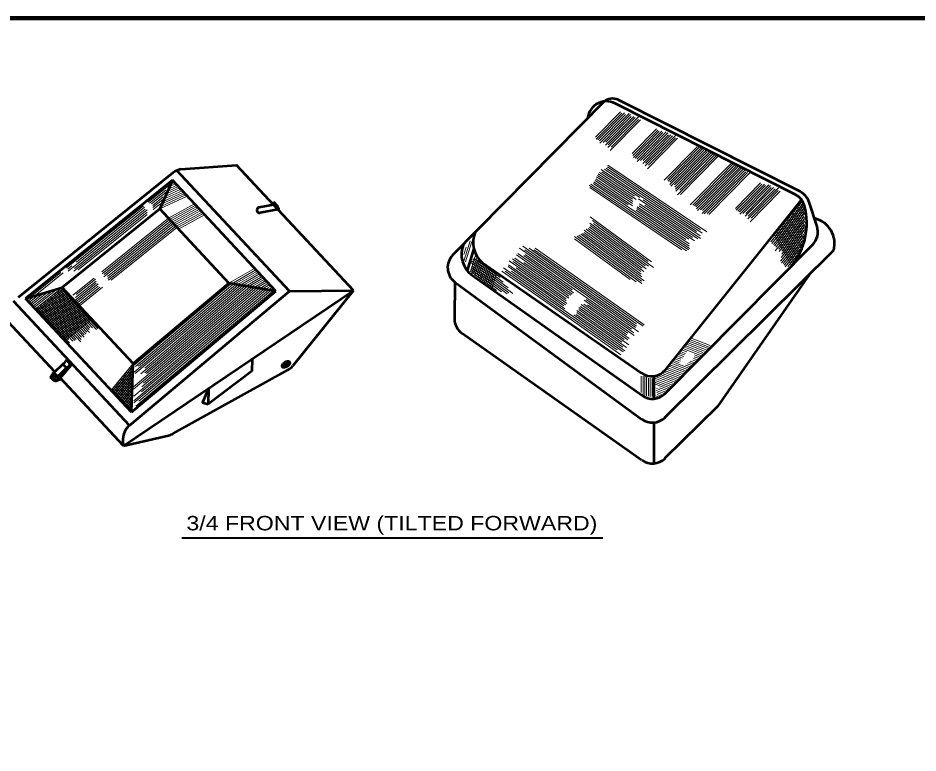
# Model space of a CAD drawing. Extents: x -94 to 619, y -64 to 390.
# Drawn here: x 121.7 to 371.6, y 180.4 to 384.5 of the extents above; entities that cross this region are included whole.
import ezdxf

# ---------------------------------------------------------------- set-up
doc = ezdxf.new("R2010")
doc.units = 0
doc.layers.add('1', color=7, linetype='Continuous', lineweight=13)

msp = doc.modelspace()

# ---------------------------------------------------------------- linework, layer by layer
at = {"layer": '1', "lineweight": 53}
for p, q in [((242.429, 318.693), (284.722, 361.553)), ((337.504, 335.457), (288.089, 360.43)), ((338.855, 336.269), (288.755, 361.588)), ((166.939, 342.485), (182.369, 343.629)), ((214.86, 308.786), (182.369, 343.629)), ((164.707, 341.463), (121.696, 306.859)), ((197.065, 308.614), (165.693, 342.257)), ((164.571, 339.428), (123.814, 306.638)), ((164.571, 339.428), (161.056, 331.467)), ((193.249, 308.675), (164.571, 339.428)), ((192.643, 332.611), (188.705, 331.907)), ((192.643, 332.611), (192.643, 333.478)), ((192.643, 333.478), (193.861, 332.172)), ((192.643, 333.111), (193.861, 331.805)), ((301.482, 286.796), (339.241, 334.004)), ((343.558, 326.638), (341.351, 333.365)), ((161.056, 331.467), (133.971, 309.675)), ((180.282, 310.849), (161.056, 331.467)), ((193.861, 331.305), (188.969, 330.43)), ((193.861, 331.305), (193.861, 332.172)), ((248.263, 320.485), (246.399, 314.394)), ((301.284, 273.599), (348.185, 319.998)), ((301.399, 280.208), (342.324, 321.525)), ((250.594, 316.631), (294.693, 285.981)), ((247.916, 312.964), (294.923, 279.733)), ((153.687, 288.533), (180.282, 310.849)), ((193.249, 308.675), (180.282, 310.849)), ((243.028, 311.151), (242.889, 301.051)), ((243.028, 311.151), (294.808, 273.124)), ((123.814, 306.638), (133.971, 309.675)), ((153.687, 288.533), (133.971, 309.675)), ((151.024, 265.729), (214.86, 308.786)), ((153.229, 275.094), (193.249, 308.675)), ((214.86, 308.786), (198.026, 287.947)), ((152.635, 271.333), (120.47, 305.825)), ((153.229, 275.094), (123.814, 306.638)), ((131.907, 286.229), (117.606, 301.565)), ((294.834, 261.694), (245.003, 296.898)), ((134.136, 288.39), (131.684, 286.012)), ((136.466, 288.11), (133.181, 284.291)), ((134.136, 288.39), (135.18, 287.313)), ((135.139, 289.525), (136.183, 288.448)), ((153.229, 275.094), (153.687, 288.533)), ((186.673, 289.774), (186.625, 286.395)), ((195.047, 287.697), (197.024, 289.115)), ((195.193, 287.494), (197.17, 288.912)), ((132.315, 283.962), (130.976, 285.188)), ((132.433, 284.609), (131.332, 285.71)), ((132.745, 284.951), (131.684, 286.012)), ((135.18, 287.313), (132.745, 284.951)), ((164.792, 269.106), (196.561, 286.715)), ((186.625, 286.395), (174.495, 277.305)), ((298.249, 285.047), (298.249, 278.776)), ((131.996, 283.561), (130.731, 284.719)), ((133.767, 284.235), (131.996, 283.561)), ((133.181, 284.291), (132.085, 283.874)), ((151.024, 265.729), (133.437, 284.588)), ((174.556, 281.601), (174.495, 277.305)), ((298.249, 272.177), (298.249, 260.805)), ((151.024, 265.729), (163.493, 268.607))]:
    msp.add_line(p, q, dxfattribs=at)
at = {"layer": '1'}
for p, q in [((282.068, 351.398), (289.033, 358.456)), ((282.248, 350.868), (289.389, 358.105)), ((282.724, 350.639), (290.118, 358.132)), ((283.175, 350.384), (290.426, 357.732)), ((283.255, 349.753), (291.355, 357.962)), ((284.158, 349.957), (291.801, 357.702)), ((284.815, 349.198), (292.654, 357.142)), ((284.908, 350.005), (291.964, 357.155)), ((285.522, 348.492), (293.987, 357.069)), ((285.565, 349.247), (293.058, 356.84)), ((286.127, 347.681), (294.502, 356.168)), ((286.394, 348.663), (293.954, 356.324)), ((292.218, 346.825), (299.033, 353.731)), ((292.423, 346.321), (299.388, 353.38)), ((292.603, 345.792), (299.744, 353.029)), ((293.079, 345.562), (300.474, 353.056)), ((293.531, 345.308), (300.782, 352.656)), ((293.611, 344.677), (301.711, 352.886)), ((294.514, 344.88), (302.157, 352.626)), ((295.17, 344.122), (303.009, 352.066)), ((295.264, 344.928), (302.32, 352.079)), ((295.878, 343.416), (304.342, 351.993)), ((295.92, 344.17), (303.413, 351.764)), ((296.483, 342.605), (304.858, 351.092)), ((296.75, 343.587), (304.309, 351.248)), ((301.143, 339.497), (310.259, 348.735)), ((302.018, 339.672), (310.86, 348.632)), ((302.248, 339.193), (311.41, 348.478)), ((302.677, 338.916), (311.887, 348.25)), ((302.706, 338.233), (312.142, 347.796)), ((302.99, 337.809), (312.645, 347.594)), ((304.007, 338.128), (313.074, 347.316)), ((304.115, 337.525), (313.674, 347.212)), ((304.244, 336.944), (314.103, 346.935)), ((304.375, 336.366), (314.533, 346.66)), ((304.834, 335.407), (315.636, 346.353)), ((305.423, 336.715), (315.158, 346.581)), ((305.608, 335.479), (315.987, 345.998)), ((283.667, 342.454), (311.085, 323.959)), ((284.512, 342.487), (310.081, 325.239)), ((285.014, 342.751), (311.648, 324.785)), ((285.347, 343.13), (311.215, 325.68)), ((285.519, 343.617), (312.943, 325.118)), ((308.36, 332.574), (319.733, 344.099)), ((309.038, 332.548), (320.384, 344.047)), ((309.565, 332.37), (320.764, 343.72)), ((309.921, 332.019), (321.267, 343.517)), ((310.073, 331.462), (321.496, 343.038)), ((310.401, 331.083), (322.125, 342.963)), ((311.205, 331.185), (322.627, 342.76)), ((311.73, 331.006), (322.981, 342.407)), ((282.315, 340.35), (292.398, 333.548)), ((282.581, 340.774), (292.299, 334.219)), ((282.798, 341.231), (293.313, 334.137)), ((283.121, 341.616), (292.848, 335.054)), ((283.766, 341.784), (294.327, 334.66)), ((311.659, 330.222), (323.485, 342.206)), ((312.239, 330.097), (323.765, 341.778)), ((313.013, 330.171), (324.268, 341.576)), ((313.517, 329.969), (324.869, 341.473)), ((163.547, 337.963), (157.813, 333.35)), ((166.187, 337.695), (163.195, 336.312)), ((165.828, 338.08), (163.501, 337.004)), ((165.469, 338.465), (163.806, 337.696)), ((165.11, 338.85), (164.112, 338.388)), ((164.751, 339.235), (164.417, 339.081)), ((280.292, 338.096), (307.327, 319.859)), ((280.463, 337.378), (305.996, 320.154)), ((280.794, 338.361), (307.896, 320.078)), ((281.492, 338.493), (308.131, 320.523)), ((281.625, 339.007), (291.164, 332.572)), ((281.958, 339.385), (292.343, 332.379)), ((282.147, 339.86), (292.364, 332.968)), ((320.909, 331.638), (327.874, 338.696)), ((321.089, 331.108), (328.23, 338.345)), ((321.565, 330.879), (328.959, 338.372)), ((322.016, 330.624), (329.267, 337.972)), ((322.096, 329.993), (330.196, 338.202)), ((322.999, 330.197), (330.642, 337.942)), ((323.656, 329.438), (331.495, 337.382)), ((323.749, 330.245), (330.805, 337.396)), ((162.718, 336.654), (158.228, 333.042)), ((162.863, 336.129), (158.793, 332.854)), ((168.699, 335.001), (161.056, 331.467)), ((168.34, 335.386), (161.362, 332.159)), ((167.981, 335.771), (161.667, 332.851)), ((167.622, 336.156), (161.973, 333.543)), ((167.263, 336.541), (162.278, 334.236)), ((166.904, 336.926), (162.584, 334.928)), ((166.546, 337.31), (162.889, 335.62)), ((324.364, 328.732), (332.828, 337.31)), ((324.406, 329.487), (331.899, 337.08)), ((324.969, 327.921), (333.344, 336.409)), ((325.235, 328.903), (332.795, 336.564)), ((162.034, 334.82), (159.101, 332.46)), ((161.984, 334.139), (159.116, 331.831)), ((161.35, 332.987), (159.236, 331.286)), ((171.031, 332.5), (163.801, 328.523)), ((294.012, 334.269), (310.456, 323.176)), ((294.305, 332.865), (309.549, 322.582)), ((295.285, 334.013), (311.176, 323.294)), ((295.738, 332.502), (309.017, 323.544)), ((330.777, 322.382), (339.77, 333.09)), ((330.831, 323.223), (339.388, 333.412)), ((338.074, 332.625), (340.712, 327.829)), ((338.419, 333.036), (340.654, 328.971)), ((338.763, 333.446), (340.499, 330.29)), ((339.108, 333.857), (340.173, 331.921)), ((156.537, 332.323), (135.164, 315.128)), ((157.037, 331.442), (135.633, 314.222)), ((157.55, 330.571), (137.242, 314.232)), ((157.523, 331.191), (137.365, 314.973)), ((156.836, 331.922), (137.935, 316.715)), ((157.546, 329.926), (138.415, 314.534)), ((171.383, 332.123), (164.153, 328.146)), ((171.734, 331.746), (164.505, 327.769)), ((172.086, 331.369), (164.856, 327.392)), ((172.438, 330.992), (165.208, 327.014)), ((172.79, 330.615), (165.56, 326.637)), ((173.141, 330.238), (165.912, 326.26)), ((293.335, 331.107), (308.098, 321.149)), ((293.552, 331.564), (308.101, 321.75)), ((293.657, 332.096), (307.115, 323.018)), ((294.186, 332.342), (307.951, 323.057)), ((331.025, 321.899), (339.753, 332.292)), ((331.448, 321.625), (339.86, 331.642)), ((331.749, 321.206), (339.921, 330.937)), ((332.08, 320.823), (340.09, 330.361)), ((336.005, 330.161), (340.098, 322.72)), ((336.35, 330.572), (340.273, 323.439)), ((336.695, 330.983), (340.426, 324.2)), ((337.039, 331.393), (340.552, 325.008)), ((337.477, 331.634), (340.647, 325.873)), ((337.729, 332.214), (340.703, 326.807)), ((163.791, 328.534), (145.056, 313.46)), ((164.475, 327.8), (145.555, 312.578)), ((164.133, 328.167), (145.612, 313.265)), ((164.817, 327.434), (146.529, 312.72)), ((173.493, 329.86), (166.263, 325.883)), ((280.504, 327.53), (296.724, 315.618)), ((280.607, 329.315), (297.631, 316.813)), ((281.254, 328.219), (296.657, 316.908)), ((281.453, 327.453), (298.117, 315.215)), ((331.901, 319.832), (339.89, 329.345)), ((332.968, 320.325), (339.971, 328.664)), ((333.074, 319.674), (339.94, 327.85)), ((333.936, 327.698), (338.696, 319.045)), ((334.281, 328.109), (338.964, 319.595)), ((334.626, 328.519), (339.22, 320.167)), ((334.971, 328.93), (339.463, 320.763)), ((335.315, 329.34), (339.691, 321.385)), ((335.66, 329.751), (339.904, 322.036)), ((165.159, 327.067), (146.657, 312.181)), ((165.501, 326.7), (146.861, 311.704)), ((165.843, 326.334), (147.593, 311.651)), ((278.938, 325.578), (294.6, 314.075)), ((278.948, 324.95), (294.744, 313.349)), ((279.452, 325.821), (295.445, 314.075)), ((280.027, 326.019), (295.015, 315.011)), ((280.347, 326.404), (296.098, 314.836)), ((280.543, 326.88), (295.842, 315.645)), ((331.867, 325.234), (336.866, 316.147)), ((332.212, 325.645), (337.195, 316.587)), ((332.557, 326.056), (337.514, 317.044)), ((332.902, 326.466), (337.825, 317.517)), ((333.246, 326.877), (338.125, 318.007)), ((333.591, 327.287), (338.416, 318.516)), ((333.611, 317.981), (339.99, 325.577)), ((333.756, 318.931), (340.087, 326.47)), ((333.775, 319.731), (340.069, 327.226)), ((247.204, 322.618), (245.475, 316.969)), ((247.682, 322.472), (245.953, 316.823)), ((276.217, 323.854), (293.383, 311.247)), ((276.265, 323.199), (291.681, 311.877)), ((276.994, 323.904), (294.924, 310.736)), ((277.432, 324.202), (294.855, 311.407)), ((277.933, 324.455), (295.544, 311.521)), ((278.447, 324.698), (294.948, 312.579)), ((331.523, 324.824), (336.504, 315.767)), ((333.4, 316.952), (339.533, 324.256)), ((333.687, 316.517), (339.925, 323.944)), ((334.175, 316.32), (339.406, 322.549)), ((246.136, 320.837), (245.513, 318.8)), ((278.244, 308.42), (260.967, 320.552)), ((293.479, 298.943), (261.884, 321.13)), ((293.164, 298.554), (262.441, 320.128)), ((292.627, 300.153), (263.601, 320.535)), ((295.3, 298.887), (265.022, 320.148)), ((295.601, 299.286), (265.309, 320.557)), ((334.415, 315.828), (339.494, 321.877)), ((334.713, 315.405), (338.808, 320.281)), ((248.831, 318.876), (247.376, 314.12)), ((249.061, 317.917), (247.703, 313.482)), ((247.997, 317.389), (256.441, 311.187)), ((249.442, 317.453), (248.207, 313.42)), ((248.293, 317.792), (255.595, 312.429)), ((271.994, 308.532), (259.016, 317.645)), ((268.896, 311.318), (259.665, 317.8)), ((275.576, 307.85), (260.137, 318.691)), ((275.969, 308.184), (260.445, 319.085)), ((275.598, 309.056), (262.138, 318.507)), ((293.449, 299.575), (264.735, 319.739)), ((335.475, 315.536), (337.874, 318.392)), ((136.627, 315.663), (135.541, 314.789)), ((180.282, 310.849), (187.393, 314.954)), ((247.405, 316.583), (259.09, 308.001)), ((247.576, 315.217), (257.539, 307.9)), ((247.701, 316.986), (257.82, 309.554)), ((247.745, 315.712), (258.007, 308.176)), ((249.756, 316.77), (248.592, 312.967)), ((250.15, 316.351), (249.025, 312.676)), ((250.531, 315.887), (249.423, 312.267)), ((250.949, 315.543), (249.799, 311.785)), ((251.392, 315.284), (250.25, 311.553)), ((251.852, 315.077), (250.721, 311.382)), ((252.33, 314.931), (251.132, 311.017)), ((275.91, 301.505), (256.494, 315.139)), ((268.997, 307.582), (257.756, 315.475)), ((269.479, 307.854), (257.92, 315.971)), ((268.298, 309.905), (258.044, 317.106)), ((269.087, 309.962), (259.172, 316.924)), ((274.096, 305.223), (259.998, 315.123)), ((268.494, 312.211), (262.178, 316.646)), ((133.587, 313.859), (125.534, 307.38)), ((134.198, 313.709), (126.893, 307.832)), ((181.057, 310.719), (187.743, 314.579)), ((181.832, 310.589), (188.093, 314.204)), ((182.607, 310.459), (188.443, 313.828)), ((183.382, 310.329), (188.793, 313.453)), ((184.157, 310.2), (189.143, 313.078)), ((184.932, 310.07), (189.493, 312.703)), ((247.299, 314.179), (254.529, 308.87)), ((247.42, 314.71), (255.959, 308.44)), ((252.808, 314.785), (251.538, 310.635)), ((253.286, 314.638), (251.974, 310.35)), ((253.764, 314.492), (252.438, 310.158)), ((253.951, 313.392), (252.834, 309.743)), ((254.425, 313.234), (253.247, 309.383)), ((275.672, 301.061), (256.959, 314.202)), ((268.345, 307.428), (258.72, 314.187)), ((143.385, 310.832), (136.878, 305.597)), ((142.801, 312.287), (136.915, 307.552)), ((143.949, 310.645), (137.191, 305.207)), ((143.968, 310.018), (137.505, 304.818)), ((143.358, 311.452), (137.673, 306.878)), ((143.197, 311.964), (137.884, 307.69)), ((153.986, 286.173), (182.78, 310.334)), ((154.008, 288.15), (180.835, 310.66)), ((154.265, 285.755), (183.428, 310.225)), ((154.329, 287.767), (181.387, 310.471)), ((155.137, 287.791), (182.131, 310.443)), ((155.8, 285.737), (184.725, 310.008)), ((156.878, 287.294), (184.076, 310.116)), ((156.878, 285.989), (185.373, 309.899)), ((185.707, 309.94), (189.843, 312.327)), ((186.482, 309.81), (190.192, 311.952)), ((187.257, 309.68), (190.542, 311.577)), ((188.032, 309.55), (190.892, 311.202)), ((188.807, 309.42), (191.243, 310.826)), ((189.582, 309.29), (191.593, 310.451)), ((190.356, 309.16), (191.942, 310.076)), ((273.932, 305.949), (268.298, 309.905)), ((273.56, 308.654), (268.494, 312.211)), ((273.952, 306.546), (269.087, 309.962)), ((126.353, 307.397), (124.498, 305.904)), ((127.623, 307.777), (124.84, 305.538)), ((128.893, 308.157), (125.182, 305.171)), ((130.162, 308.536), (125.524, 304.804)), ((131.432, 308.916), (125.865, 304.438)), ((132.701, 309.296), (126.207, 304.071)), ((133.971, 309.675), (126.549, 303.704)), ((134.284, 309.286), (126.891, 303.338)), ((134.598, 308.896), (127.233, 302.971)), ((134.997, 308.575), (127.575, 302.605)), ((135.338, 308.209), (127.917, 302.238)), ((135.68, 307.842), (128.259, 301.871)), ((136.022, 307.476), (128.601, 301.505)), ((140.788, 297.233), (131.237, 307.476)), ((141.514, 297.188), (131.627, 307.79)), ((141.42, 298.022), (132.018, 308.104)), ((141.651, 298.507), (132.408, 308.418)), ((142.383, 298.454), (132.799, 308.733)), ((143.527, 297.961), (133.19, 309.047)), ((143.893, 298.302), (133.58, 309.361)), ((144.432, 309.749), (137.818, 304.428)), ((145.205, 309.729), (138.131, 304.039)), ((153.743, 281.4), (187.318, 309.573)), ((153.75, 282.059), (186.67, 309.682)), ((153.816, 278.198), (190.464, 308.949)), ((153.838, 279.522), (189.263, 309.247)), ((153.904, 277.619), (191.208, 308.921)), ((154.42, 276.746), (192.45, 308.658)), ((155.29, 278.13), (191.856, 308.812)), ((155.964, 280.653), (189.815, 309.058)), ((156.113, 282.084), (188.519, 309.275)), ((156.526, 283.082), (187.966, 309.464)), ((157.394, 285.769), (186.021, 309.79)), ((187.037, 303.463), (192.867, 308.355)), ((191.131, 309.03), (192.292, 309.7)), ((191.906, 308.9), (192.642, 309.325)), ((192.681, 308.77), (192.992, 308.95)), ((273.574, 303.756), (268.345, 307.428)), ((273.273, 304.579), (268.997, 307.581)), ((273.715, 304.88), (269.479, 307.854)), ((274.647, 306.669), (271.994, 308.532)), ((275.164, 307.528), (273.56, 308.654)), ((293.971, 297.376), (278.244, 308.42)), ((125.084, 307.017), (124.156, 306.271)), ((137.443, 294.954), (128.112, 304.962)), ((137.873, 295.227), (128.502, 305.276)), ((139.163, 294.576), (128.893, 305.59)), ((136.364, 307.109), (128.943, 301.138)), ((139.211, 295.258), (129.283, 305.904)), ((136.706, 306.742), (129.285, 300.771)), ((137.048, 306.376), (129.626, 300.405)), ((139.287, 295.909), (129.674, 306.219)), ((137.39, 306.009), (129.968, 300.038)), ((140.031, 295.845), (130.065, 306.533)), ((137.732, 305.642), (130.31, 299.671)), ((140.059, 296.548), (130.455, 306.847)), ((138.074, 305.276), (130.652, 299.305)), ((140.526, 296.78), (130.846, 307.161)), ((138.416, 304.909), (130.994, 298.938)), ((290.789, 296.556), (278.768, 304.997)), ((292.802, 296.364), (278.882, 306.138)), ((292.668, 297.069), (279.425, 306.369)), ((135.985, 294.319), (126.94, 304.019)), ((135.855, 295.192), (127.33, 304.333)), ((136.905, 294.799), (127.721, 304.647)), ((138.758, 304.542), (131.336, 298.571)), ((139.1, 304.176), (131.678, 298.205)), ((139.441, 303.809), (132.02, 297.838)), ((139.783, 303.442), (132.362, 297.471)), ((140.125, 303.076), (132.704, 297.105)), ((140.467, 302.709), (133.046, 296.738)), ((290.623, 293.006), (276.825, 302.696)), ((289.372, 294.496), (276.865, 303.278)), ((291.316, 293.741), (277.407, 303.508)), ((279.29, 302.798), (277.444, 304.094)), ((280.267, 302.723), (277.879, 304.399)), ((290.048, 295.243), (279.29, 302.798)), ((291.038, 296.992), (279.828, 304.864)), ((291.041, 295.157), (280.267, 302.722)), ((140.809, 302.342), (133.387, 296.371)), ((141.151, 301.976), (133.729, 296.005)), ((141.493, 301.609), (134.071, 295.638)), ((141.835, 301.242), (134.413, 295.272)), ((142.177, 300.876), (134.755, 294.905)), ((289.12, 291.007), (275.385, 300.652)), ((288.077, 292.35), (275.615, 301.101)), ((289.69, 291.829), (275.91, 301.505)), ((290.202, 292.08), (276.034, 302.029)), ((289.605, 293.11), (276.648, 302.209)), ((278.702, 302.082), (279.042, 301.833)), ((308.634, 295.037), (313.606, 293.121)), ((308.926, 295.46), (313.868, 293.556)), ((306.743, 292.551), (311.519, 290.71)), ((307.023, 292.979), (311.698, 291.177)), ((307.15, 293.466), (311.89, 291.639)), ((307.389, 293.909), (312.301, 292.016)), ((307.786, 294.292), (313.015, 292.277)), ((307.973, 294.756), (313.588, 292.592)), ((304.649, 290.143), (305.727, 289.727)), ((305.066, 290.518), (306.223, 290.072)), ((305.257, 290.98), (306.594, 290.465)), ((305.407, 291.458), (306.77, 290.933)), ((306.046, 291.747), (307.066, 291.354)), ((306.166, 292.237), (307.38, 291.769)), ((309.253, 289.976), (310.09, 289.653)), ((309.468, 290.429), (310.538, 290.017)), ((309.534, 290.939), (311.066, 290.349)), ((153.687, 288.533), (147.553, 281.181)), ((153.659, 287.719), (147.937, 280.861)), ((153.638, 287.118), (153.041, 287.759)), ((153.663, 287.825), (153.364, 288.146)), ((302.665, 287.692), (306.95, 286.041)), ((302.977, 288.107), (307.338, 286.427)), ((303.413, 288.476), (307.577, 286.871)), ((303.672, 288.911), (307.989, 287.248)), ((303.981, 289.328), (305.329, 288.809)), ((304.271, 289.752), (305.626, 289.23)), ((307.072, 288.137), (308.46, 287.602)), ((307.524, 288.499), (308.86, 287.984)), ((307.966, 288.864), (309.301, 288.35)), ((308.362, 289.247), (309.641, 288.754)), ((309.077, 289.508), (309.713, 289.263)), ((153.631, 286.905), (148.24, 280.444)), ((153.603, 286.092), (148.584, 280.075)), ((153.576, 285.278), (148.928, 279.707)), ((153.47, 282.167), (150.781, 285.05)), ((153.494, 282.874), (151.104, 285.437)), ((153.518, 283.582), (151.427, 285.824)), ((153.542, 284.289), (151.75, 286.211)), ((153.566, 284.996), (152.072, 286.598)), ((153.59, 285.703), (152.395, 286.985)), ((153.614, 286.411), (152.718, 287.372)), ((294.749, 285.047), (294.749, 280.466)), ((295.249, 285.047), (295.249, 280.008)), ((295.749, 285.047), (295.749, 279.794)), ((296.249, 285.047), (296.249, 279.549)), ((299.634, 285.109), (304.144, 283.371)), ((300.29, 285.392), (304.638, 283.717)), ((300.826, 285.721), (304.769, 284.202)), ((301.282, 286.082), (305.364, 284.508)), ((301.711, 286.452), (305.573, 284.964)), ((301.987, 286.882), (306.187, 285.263)), ((302.342, 287.281), (306.254, 285.773)), ((153.325, 277.923), (148.844, 282.728)), ((153.349, 278.631), (149.167, 283.115)), ((153.548, 284.464), (149.271, 279.338)), ((153.373, 279.338), (149.49, 283.502)), ((153.52, 283.65), (149.615, 278.969)), ((153.397, 280.045), (149.813, 283.889)), ((153.493, 282.837), (149.959, 278.601)), ((153.422, 280.752), (150.136, 284.276)), ((153.446, 281.46), (150.458, 284.663)), ((296.749, 284.532), (296.749, 279.519)), ((297.249, 284.502), (297.249, 279.427)), ((297.749, 284.41), (297.749, 279.427)), ((298.684, 283.332), (302.443, 281.883)), ((298.693, 282.793), (302.192, 281.444)), ((298.719, 284.39), (303.438, 282.572)), ((298.918, 284.849), (303.505, 283.082)), ((298.928, 283.774), (302.962, 282.219)), ((153.253, 275.802), (147.876, 281.568)), ((153.277, 276.509), (148.241, 281.909)), ((153.301, 277.216), (148.521, 282.342)), ((153.465, 282.023), (150.302, 278.232)), ((153.437, 281.209), (150.646, 277.864)), ((153.409, 280.395), (150.99, 277.495)), ((298.919, 281.098), (300.91, 280.331)), ((299.034, 281.589), (301.328, 280.705)), ((299.061, 280.507), (300.327, 280.02)), ((299.219, 279.91), (299.821, 279.679)), ((299.838, 281.815), (301.662, 281.113)), ((153.382, 279.582), (151.333, 277.127)), ((153.354, 278.768), (151.677, 276.758)), ((153.326, 277.954), (152.021, 276.39)), ((298.76, 279.551), (299.591, 279.231)), ((153.298, 277.14), (152.364, 276.021)), ((153.271, 276.327), (152.708, 275.653))]:
    msp.add_line(p, q, dxfattribs=at)
at = {"layer": '1', "lineweight": 40}
msp.add_line((167.143, 240.135), (284.122, 240.135), dxfattribs=at)
at = {"layer": '1', "lineweight": 158}
msp.add_lwpolyline([(613.334, 384.481), (-46.416, 384.397), (-46.333, -53.936)], dxfattribs=at)
at = {"layer": '1'}
for points in [[(170.679, 332.878), (163.45, 328.9), (144.971, 314.034)], [(292.089, 298.087), (277.787, 308.13), (262.496, 318.867)], [(275.385, 300.652), (268.529, 305.467), (256.069, 314.216)], [(274.679, 307.257), (272.482, 308.8), (268.896, 311.318)], [(291.404, 295.513), (282.139, 302.019), (278.039, 304.898)]]:
    msp.add_lwpolyline(points, dxfattribs=at)
at = {"layer": '1', "lineweight": 53}
for points in [[(341.542, 313.426), (315.906, 276.668), (301.227, 262.215)], [(152.635, 271.333), (197.065, 308.614), (214.86, 308.786)], [(174.556, 281.601), (172.934, 277.689), (174.495, 277.305)]]:
    msp.add_lwpolyline(points, dxfattribs=at)
for centre, radius, start, end in [((285.1, 356.088), 5.271, 55.45095, 174.18638), ((286.768, 358.108), 4.007, 60.28803, 120.71357), ((167.841, 337.567), 5, 100.4008, 128.81759), ((335.248, 330.995), 5, 15.07312, 63.18927), ((336.6, 331.806), 5, 18.17013, 63.18958), ((188.765, 331.156), 0.754, 94.57729, 285.70271), ((193.603, 331.327), 0.543, 329.79385, 61.6922), ((322.147, 327.466), 18.568, 320.7657, 15.07312), ((341.265, 321.86), 7.167, 344.94334, 75.45461), ((255.445, 322.198), 7.384, 157.88916, 228.93353), ((338.808, 325.079), 5, 314.69118, 18.17057), ((252.078, 318.901), 7.25, 157.67897, 234.96895), ((245.988, 315.181), 5, 135.38136, 233.70593), ((247.888, 300.982), 5, 179.20851, 234.75943), ((132.774, 290.603), 2.599, 301.61144, 335.47975), ((135.221, 288.56), 0.969, 353.37461, 94.84721), ((133.975, 289.388), 2.399, 300.15332, 336.93786), ((135.219, 288.196), 1.25, 356.04932, 56.10446), ((194.137, 291.089), 5, 299.00019, 321.06979), ((131.964, 284.375), 1.28, 111.86801, 164.43877), ((131.645, 285.702), 0.313, 82.91008, 178.42882), ((132.435, 284.921), 0.311, 269.67074, 5.67221), ((297.653, 290.011), 5, 233.70535, 319.97622), ((132.231, 283.663), 0.257, 124.68143, 203.51235), ((133.115, 284.788), 0.502, 193.01078, 277.55203), ((297.882, 283.763), 5, 233.70593, 314.69088), ((297.882, 277.164), 5, 233.70564, 314.69135), ((156.068, 267.319), 5.289, 124.21058, 197.49633), ((162.368, 273.479), 5, 283.00061, 299.00053), ((297.842, 265.789), 5, 234.75966, 314.55799)]:
    msp.add_arc(centre, radius, start, end, dxfattribs=at)
at = {"layer": '1'}
msp.add_arc((167.841, 337.567), 5, 100.40084, 128.81858, dxfattribs=at)
at = {"layer": '1', "lineweight": 53}
msp.add_ellipse((196.108, 288.305), major_axis=(1.006, 0.722), ratio=0.545523, dxfattribs=at)

# ---------------------------------------------------------------- texts
at = {"layer": '1', "width": 1.2}
msp.add_text('3/4 FRONT VIEW (TILTED FORWARD)', height=4, dxfattribs=at).set_placement((168.458, 242.239))

doc.saveas('drawing.dxf')
